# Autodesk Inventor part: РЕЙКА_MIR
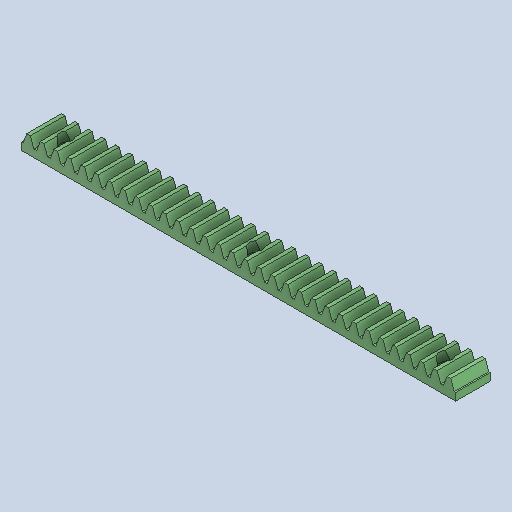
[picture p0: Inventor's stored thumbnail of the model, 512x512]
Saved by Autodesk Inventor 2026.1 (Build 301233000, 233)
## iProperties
Created: 2025-11
Part Number: РЕЙКА_MIR
Material: Steel
Document SubType Name: Modeling
Designer: Yury Melnikov
Density: 7.85 g/cm^3
Appearance: По умолчанию
Title: m2_20.step
Sending System: Autodesk Translation Framework v14.17.0.0
Preprocessor: ST-DEVELOPER v20.1
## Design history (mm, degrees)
derived "РЕЙКА.ipt"
  sketch "Эскиз1"
    geometry: L1 (0, 0)-(-201.062, 0) reference; L2 (-201.062, 0)-(-201.062, 16) reference; L3 (0, 16)-(-201.062, 16) reference; L4 (0, 0)-(0, 16) reference; C1 r 1.35 at (-12.566, 8) reference; C2 r 1.35 at (-100.531, 8) reference; C3 r 1.35 at (-188.496, 8) reference; 1 further point
    dimensions: "d0" = 10 dimension on point (191.959, 0) L1.start L1.end L2.end L3.start L1 L2 L3 L4 C1.centre C1 C2.centre C2 C3.centre C3
feature "Твердое тело1::РЕЙКА.ipt" dims "d0" = 10
tag "Элемент создания тегов1"
node "Твердое тело1"
